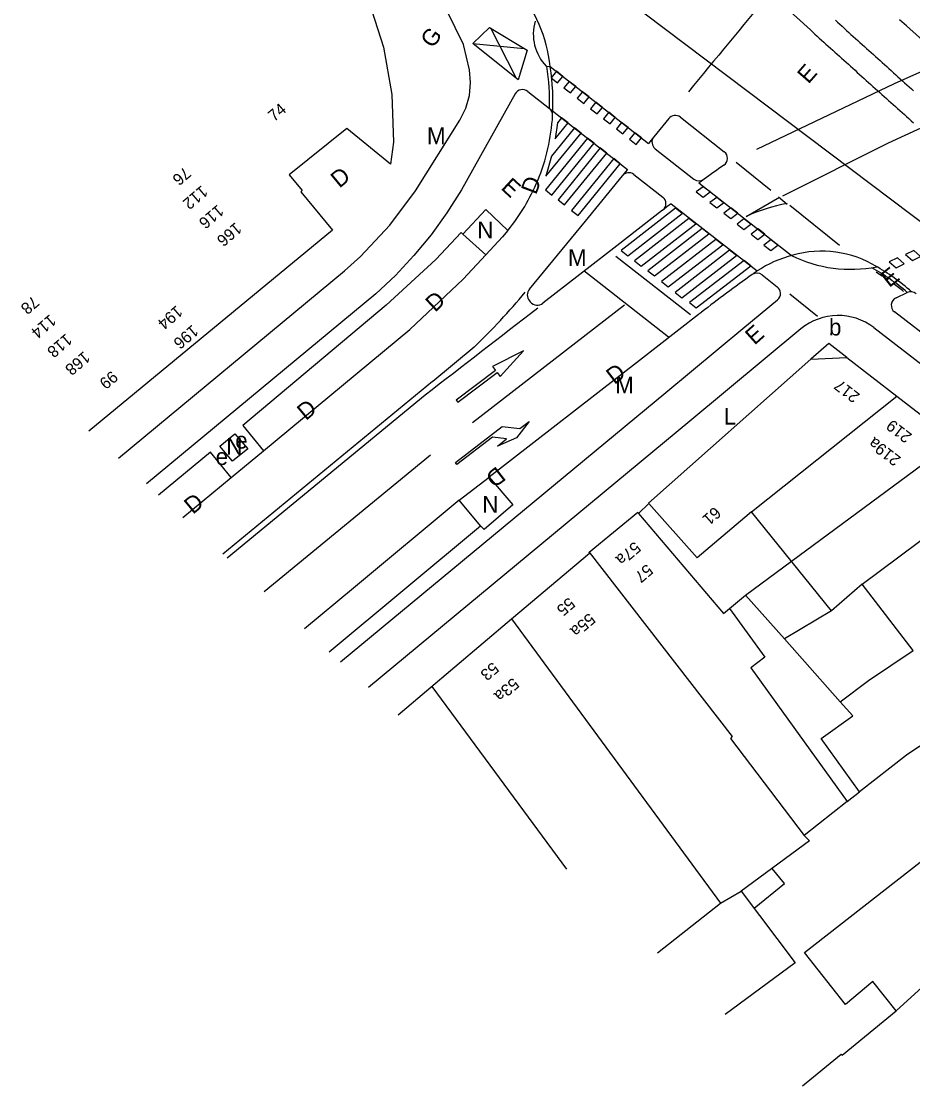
# Model space of a CAD drawing. Extents: x 81617 to 82144, y 454649 to 455150.
# Drawn here: x 81644.1 to 81697.5, y 454675.9 to 454739.6 of the extents above; entities that cross this region are included whole.
import ezdxf

# ---------------------------------------------------------------- set-up
doc = ezdxf.new("R2010")
doc.units = 0
doc.layers.add('B-WE-OG-TOPOGRAFIE-G', color=7, linetype='Continuous')
doc.layers.add('B-WE-VW-MARKERING-G', color=7, linetype='Continuous')

msp = doc.modelspace()

# ---------------------------------------------------------------- linework, layer by layer
at = {"layer": 'B-WE-OG-TOPOGRAFIE-G'}
for p, q in [((81675.519, 454736.911), (81675.741, 454736.896)), ((81675.741, 454736.896), (81681.634, 454732.285)), ((81674.403, 454735.404), (81675.706, 454734.384)), ((81675.706, 454734.384), (81680.373, 454730.732)), ((81682.848, 454733.778), (81681.955, 454732.68)), ((81683.544, 454733.856), (81686.175, 454731.792)), ((81681.955, 454732.68), (81681.634, 454732.285)), ((81682.035, 454731.971), (81684.36, 454730.151)), ((81680.063, 454730.351), (81677.85, 454727.627)), ((81680.373, 454730.732), (81680.063, 454730.351)), ((81680.76, 454730.43), (81682.487, 454729.078)), ((81684.657, 454729.919), (81690.172, 454725.604)), ((81682.995, 454728.68), (81688.146, 454724.65)), ((81677.85, 454727.627), (81674.501, 454723.568)), ((81671.903, 454725.607), (81670.521, 454726.86)), ((81688.439, 454724.42), (81689.35, 454723.708)), ((81665.305, 454723.274), (81651.571, 454711.895)), ((81696.457, 454723.047), (81697.123, 454723.364)), ((81674.509, 454722.859), (81674.561, 454722.798)), ((81684.628, 454722.04), (81681.091, 454719.294)), ((81699.533, 454719.756), (81696.366, 454722.2)), ((81692.444, 454720.301), (81691.36, 454719.373)), ((81693.506, 454719.47), (81692.444, 454720.301)), ((81687.809, 454710.22), (81696.504, 454717.158)), ((81690.199, 454707.264), (81699.968, 454714.488)), ((81656.655, 454712.276), (81658.584, 454713.883)), ((81653.762, 454709.885), (81656.655, 454712.276)), ((81670.307, 454710.92), (81672.094, 454712.308)), ((81671.585, 454709.381), (81670.307, 454710.92)), ((81681.045, 454710.132), (81681.659, 454710.717)), ((81694.423, 454705.904), (81700, 454710.044)), ((81662.521, 454701.853), (81671.585, 454709.381)), ((81686.485, 454704.429), (81687.454, 454705.234)), ((81673.439, 454703.812), (81685.954, 454686.794)), ((81689.771, 454702.623), (81693.12, 454698.851)), ((81693.53, 454692.873), (81694.275, 454693.457)), ((81689.77, 454687.969), (81689.035, 454688.872)), ((81685.954, 454686.794), (81687.192, 454687.509)), ((81687.958, 454686.496), (81689.77, 454687.969)), ((81696.461, 454680.345), (81700, 454683.576))]:
    msp.add_line(p, q, dxfattribs=at)
for points in [[(81666.167, 454761.826), (81691.328, 454739.082), (81691.328, 454739.082), (81691.461, 454738.961), (81691.595, 454738.84), (81691.729, 454738.719), (81691.863, 454738.598), (81691.996, 454738.478), (81692.13, 454738.357), (81692.264, 454738.236), (81692.398, 454738.115), (81692.532, 454737.994), (81692.665, 454737.873), (81692.799, 454737.752), (81692.933, 454737.631), (81693.067, 454737.51), (81693.201, 454737.39), (81693.335, 454737.269), (81693.468, 454737.148), (81693.602, 454737.027), (81693.736, 454736.906), (81693.87, 454736.785), (81694.004, 454736.665), (81694.138, 454736.544), (81694.272, 454736.423), (81694.406, 454736.302), (81694.54, 454736.182), (81694.674, 454736.061), (81694.808, 454735.94), (81694.942, 454735.819), (81695.076, 454735.699), (81695.21, 454735.578), (81695.344, 454735.457), (81695.479, 454735.337), (81695.613, 454735.216), (81695.747, 454735.096), (81695.881, 454734.975), (81696.016, 454734.855), (81696.15, 454734.734), (81696.284, 454734.614), (81696.418, 454734.493), (81696.553, 454734.373), (81696.553, 454734.373), (81696.687, 454734.252), (81696.822, 454734.132), (81696.956, 454734.011), (81697.091, 454733.891), (81697.226, 454733.771), (81697.36, 454733.65), (81697.495, 454733.53)], [(81670.568, 454738.214), (81669.091, 454741.249), (81668.201, 454742.903), (81667.143, 454744.591), (81666.308, 454745.728), (81665.415, 454746.82), (81664.464, 454747.862)], [(81664.894, 454740.79), (81665.775, 454738.056), (81666.269, 454735.227), (81666.365, 454732.357), (81666.198, 454731.046), (81663.567, 454733.177), (81660.121, 454730.415), (81660.901, 454729.465), (81660.815, 454729.388), (81662.719, 454727.096)], [(81692.825, 454739.663), (81692.959, 454739.542), (81693.092, 454739.421), (81693.226, 454739.3), (81693.36, 454739.18), (81693.494, 454739.059), (81693.627, 454738.938), (81693.761, 454738.817), (81693.895, 454738.696), (81694.029, 454738.576), (81694.162, 454738.455), (81694.296, 454738.334), (81694.43, 454738.213), (81694.564, 454738.092), (81694.697, 454737.972), (81694.831, 454737.851), (81694.965, 454737.73), (81695.099, 454737.61), (81695.233, 454737.489), (81695.367, 454737.368), (81695.5, 454737.248), (81695.634, 454737.127), (81695.768, 454737.007), (81695.902, 454736.886), (81696.036, 454736.765), (81696.17, 454736.645), (81696.304, 454736.524), (81696.438, 454736.404), (81696.572, 454736.284), (81696.706, 454736.163), (81696.84, 454736.043), (81696.974, 454735.922), (81697.108, 454735.802), (81697.242, 454735.682), (81697.376, 454735.562), (81697.51, 454735.441)], [(81731.982, 454708.032), (81697.077, 454739.337), (81697.077, 454739.337), (81696.942, 454739.457), (81696.808, 454739.577), (81696.674, 454739.698)], [(81667.684, 454729.457), (81670.339, 454733.689), (81670.694, 454734.393), (81670.923, 454735.155), (81670.986, 454735.928), (81670.928, 454736.691), (81670.568, 454738.214)], [(81673.659, 454735.254), (81670.435, 454729.503), (81669.57, 454728.132)], [(81649.895, 454713.432), (81663.43, 454724.654), (81664.386, 454725.517), (81666.145, 454727.394), (81667.684, 454729.457)], [(81670.521, 454726.86), (81671.896, 454728.323), (81673.215, 454727.075)], [(81682.484, 454728.289), (81679.734, 454726.153)], [(81669.57, 454728.132), (81668.621, 454726.819), (81667.591, 454725.568), (81666.484, 454724.385), (81665.305, 454723.274)], [(81662.719, 454727.096), (81648.125, 454715.055)], [(81670.521, 454726.86), (81670.425, 454726.948), (81668.903, 454725.346), (81665.935, 454722.606), (81657.348, 454715.394), (81658.584, 454713.883)], [(81673.215, 454727.075), (81672.899, 454726.686), (81671.903, 454725.607)], [(81673.215, 454727.075), (81672.899, 454726.686), (81671.903, 454725.607)], [(81679.734, 454726.153), (81675.316, 454722.723)], [(81658.584, 454713.883), (81667.339, 454721.154), (81670.536, 454724.153), (81671.903, 454725.607)], [(81682.675, 454717.381), (81687.29, 454721.203), (81689.362, 454722.93)], [(81690.761, 454721.18), (81684.105, 454715.66)], [(81695.133, 454721.257), (81710.923, 454709.073), (81719.683, 454702.175)], [(81681.091, 454719.294), (81672.094, 454712.308)], [(81681.659, 454710.717), (81681.638, 454710.746), (81691.36, 454719.373), (81693.506, 454719.47), (81696.504, 454717.158), (81700, 454714.463)], [(81663.187, 454701.242), (81682.675, 454717.381)], [(81684.105, 454715.66), (81664.864, 454699.703)], [(81657.638, 454713.992), (81656.728, 454713.26), (81655.96, 454714.155), (81656.866, 454714.904), (81657.638, 454713.992)], [(81656.655, 454712.276), (81655.406, 454713.794), (81652.298, 454711.228)], [(81672.094, 454712.308), (81673.52, 454710.648), (81671.789, 454709.162), (81671.585, 454709.381)], [(81670.307, 454710.92), (81663.97, 454705.661), (81661.031, 454703.219)], [(81700, 454693.76), (81699.888, 454693.884), (81697.881, 454696.204), (81697.087, 454695.661), (81694.275, 454693.457), (81691.968, 454696.655), (81693.864, 454698.013), (81693.12, 454698.851), (81694.811, 454700.118), (81697.487, 454701.918), (81694.423, 454705.904), (81692.598, 454704.296), (81687.809, 454710.22), (81687.395, 454709.889), (81684.558, 454707.482), (81681.659, 454710.717)], [(81666.647, 454698.069), (81673.439, 454703.812), (81678.1, 454707.752), (81678.082, 454707.815), (81680.988, 454710.202), (81681.045, 454710.132)], [(81681.045, 454710.132), (81686.127, 454704.132), (81686.485, 454704.429), (81688.598, 454701.527), (81687.773, 454700.88), (81693.53, 454692.873), (81690.948, 454690.849), (81691.274, 454690.528), (81687.192, 454687.509), (81690.426, 454683.228), (81686.219, 454680.119)], [(81678.082, 454707.815), (81686.64, 454696.766), (81686.54, 454696.658), (81690.948, 454690.849)], [(81692.598, 454704.296), (81689.771, 454702.623), (81687.454, 454705.234), (81690.199, 454707.264)], [(81668.655, 454699.767), (81676.731, 454688.82)], [(81690.86, 454675.862), (81693.167, 454677.748), (81693.226, 454677.694), (81696.461, 454680.345), (81695.069, 454682.109), (81693.441, 454680.727), (81690.98, 454683.836), (81700, 454690.889)], [(81682.179, 454683.824), (81685.954, 454686.794)]]:
    msp.add_lwpolyline(points, dxfattribs=at)
for centre, radius, start, end in [((81667.367, 454736.072), 8.414, 5.61736, 41.24927), ((81677.483, 454738.825), 2.743, 163.56997, 224.26272), ((81674.095, 454735.01), 0.5, 51.95732, 150.7285), ((81663.917, 454734.661), 12, 337.46595, 356.65409), ((81675.398, 454733.99), 0.5, 356.65409, 51.95732), ((81683.236, 454733.463), 0.5, 51.87473, 140.91169), ((81682.343, 454732.365), 0.5, 140.91169, 231.95732), ((81685.866, 454731.399), 0.5, 305.04981, 51.87473), ((81743.582, 454649.124), 100, 125.04981, 125.88829), ((81680.452, 454730.036), 0.5, 51.95732, 140.91169), ((81684.669, 454730.545), 0.5, 231.95732, 305.88829), ((81743.582, 454649.124), 100, 125.88829, 126.10378), ((81663.917, 454734.661), 12, 320.91169, 337.46595), ((81682.179, 454728.684), 0.5, 307.66054, 51.95732), ((81743.582, 454649.124), 100, 127.2916, 127.66054), ((81692.001, 454719.529), 6.308, 58.38506, 105.91347), ((81692.031, 454718.774), 7.044, 104.46027, 123.46789), ((81693.748, 454732.794), 8.046, 243.79663, 281.17558), ((81745.959, 454643.057), 100, 125.53419, 127.69775), ((81688.131, 454724.027), 0.5, 51.95732, 125.53419), ((81692.104, 454718.876), 7, 124.43137, 127.06323), ((81674.926, 454723.218), 0.55, 140.4727, 220.72473), ((81689.042, 454723.314), 0.5, 309.80557, 51.95732), ((81697.338, 454722.913), 0.5, 48.09943, 115.44696), ((81674.978, 454723.157), 0.55, 220.72473, 307.82968), ((81696.672, 454722.596), 0.5, 115.44696, 232.34591), ((81745.959, 454643.057), 100, 127.69775, 127.82968), ((81692.995, 454718.486), 3.5, 52.34591, 129.66966)]:
    msp.add_arc(centre, radius, start, end, dxfattribs=at)
at = {"layer": 'B-WE-VW-MARKERING-G'}
for p, q in [((81678.314, 454742.411), (81698.634, 454727.077)), ((81672.168, 454739.2), (81673.672, 454736.267)), ((81671.123, 454738.267), (81674.199, 454737.97)), ((81687.488, 454727.919), (81689.477, 454729.074)), ((81689.423, 454729.088), (81689.934, 454728.65)), ((81677.755, 454724.677), (81682.831, 454720.705)), ((81671.099, 454715.57), (81680.196, 454722.623)), ((81671.201, 454720.085), (81668.716, 454718.027)), ((81668.713, 454718.03), (81656.154, 454707.692)), ((81668.272, 454717.21), (81656.409, 454707.458)), ((81674.489, 454715.636), (81673.723, 454714.665)), ((81673.935, 454715.208), (81674.489, 454715.636)), ((81670.075, 454713.171), (81672.883, 454715.343)), ((81672.883, 454715.343), (81673.935, 454715.208)), ((81672.303, 454714.704), (81670.167, 454713.053)), ((81673.144, 454714.597), (81672.303, 454714.704)), ((81673.723, 454714.665), (81672.591, 454714.168)), ((81672.591, 454714.168), (81673.144, 454714.597)), ((81668.579, 454713.628), (81658.622, 454705.429)), ((81670.167, 454713.053), (81670.075, 454713.171))]:
    msp.add_line(p, q, dxfattribs=at)
for points in [[(81689.688, 454729.154), (81696.008, 454732.316), (81704.216, 454736.092), (81716.472, 454741.453)], [(81688.131, 454731.94), (81696.375, 454735.872), (81698.635, 454736.901)], [(81686.876, 454731.173), (81688.964, 454729.498)], [(81690.094, 454728.592), (81693.07, 454726.204)], [(81679.685, 454725.535), (81684.153, 454722.039)], [(81690.09, 454723.277), (81691.765, 454721.934)]]:
    msp.add_lwpolyline(points, dxfattribs=at)
for points in [[(81671.123, 454738.267), (81672.109, 454739.227), (81674.37, 454737.862), (81673.834, 454736.095)], [(81676.512, 454736.299), (81676.118, 454736.607), (81675.802, 454736.219), (81676.196, 454735.911)], [(81677.284, 454735.695), (81676.89, 454736.003), (81676.575, 454735.615), (81676.968, 454735.307)], [(81678.082, 454735.07), (81677.689, 454735.378), (81677.373, 454734.99), (81677.767, 454734.682)], [(81678.881, 454734.445), (81678.487, 454734.753), (81678.172, 454734.365), (81678.566, 454734.057)], [(81679.649, 454733.845), (81679.255, 454734.153), (81678.94, 454733.765), (81679.334, 454733.456)], [(81676.826, 454733.514), (81676.432, 454733.822), (81676.191, 454733.526), (81676.055, 454732.565)], [(81680.421, 454733.241), (81680.027, 454733.549), (81679.712, 454733.161), (81680.106, 454732.853)], [(81677.598, 454732.91), (81677.204, 454733.218), (81675.828, 454731.524), (81675.498, 454730.325)], [(81681.215, 454732.619), (81680.821, 454732.927), (81680.506, 454732.539), (81680.9, 454732.231)], [(81678.379, 454732.299), (81677.985, 454732.607), (81675.462, 454729.502), (81675.856, 454729.194)], [(81679.138, 454731.706), (81678.744, 454732.014), (81676.222, 454728.909), (81676.615, 454728.601)], [(81679.95, 454731.07), (81679.556, 454731.378), (81677.033, 454728.273), (81677.427, 454727.965)], [(81685.322, 454729.379), (81684.913, 454729.698), (81684.498, 454729.389), (81684.906, 454729.069)], [(81686.135, 454728.736), (81685.727, 454729.056), (81685.311, 454728.746), (81685.719, 454728.427)], [(81683.662, 454728.086), (81683.254, 454728.406), (81679.992, 454725.879), (81680.398, 454725.561)], [(81686.978, 454728.103), (81686.57, 454728.422), (81686.154, 454728.113), (81686.562, 454727.793)], [(81684.465, 454727.469), (81684.057, 454727.789), (81680.796, 454725.262), (81681.202, 454724.944)], [(81687.759, 454727.452), (81687.351, 454727.771), (81686.936, 454727.462), (81687.344, 454727.142)], [(81685.257, 454726.876), (81684.849, 454727.195), (81681.588, 454724.668), (81681.994, 454724.351)], [(81688.603, 454726.849), (81688.195, 454727.168), (81687.779, 454726.858), (81688.187, 454726.539)], [(81686.08, 454726.218), (81685.672, 454726.537), (81682.411, 454724.01), (81682.817, 454723.693)], [(81689.375, 454726.194), (81688.967, 454726.513), (81688.551, 454726.204), (81688.959, 454725.884)], [(81686.897, 454725.573), (81686.489, 454725.892), (81683.227, 454723.365), (81683.634, 454723.048)], [(81697.927, 454725.519), (81697.52, 454725.879), (81697.029, 454725.645), (81697.436, 454725.285)], [(81687.764, 454724.965), (81687.355, 454725.284), (81684.094, 454722.757), (81684.5, 454722.439)], [(81696.948, 454725.075), (81696.541, 454725.435), (81696.051, 454725.202), (81696.458, 454724.841)], [(81674.156, 454719.868), (81672.295, 454718.93), (81672.476, 454718.691), (81670.123, 454716.911), (81670.214, 454716.791), (81672.566, 454718.571), (81672.747, 454718.332)]]:
    msp.add_lwpolyline(points, close=True, dxfattribs=at)
for centre, radius, start, end in [((83492.28, 453246.905), 2342.079, 140.169378, 140.540083), ((81661.389, 454734.734), 14.328, 358.57939, 8.73167), ((81661.389, 454734.734), 14.528, 356.95176, 8.50812), ((81692.014, 454717.772), 11.111, 100.81313, 114.04018), ((81688.818, 454713.695), 12.751, 49.32793, 60.98455), ((81688.818, 454713.695), 12.951, 48.60466, 60.40218), ((81688.437, 454713.023), 13.414, 55.75821, 59.41292), ((81688.437, 454713.023), 13.414, 50.80229, 54.18653), ((81639.242, 454752.805), 45.741, 314.32623, 319.95347), ((82380.944, 453802.794), 1159.334, 127.511498, 127.931913)]:
    msp.add_arc(centre, radius, start, end, dxfattribs=at)

# ---------------------------------------------------------------- texts
at = {"layer": 'B-WE-OG-TOPOGRAFIE-G'}
for s, height, rotation, p in [('G', 1, 54.20164, (81668.72, 454737.937)), ('E', 1, 48.83265, (81691.21, 454735.81)), ('74', 0.7, 40.11061, (81659.22, 454733.555)), ('76', 0.7, 220.3698, (81653.864, 454730.919)), ('D', 1, 39.55066, (81663.129, 454729.573)), ('E', 1, 317.23229, (81672.752, 454729.583)), ('D', 1, 69.18376, (81674.903, 454729.173)), ('112', 0.7, 220.3698, (81654.883, 454729.816)), ('116', 0.7, 220.3698, (81655.841, 454728.661)), ('166', 0.7, 220.3698, (81656.915, 454727.606)), ('E', 1, 38.51962, (81696.05, 454723.623)), ('78', 0.7, 220.3698, (81644.78, 454723.196)), ('D', 1, 43.36353, (81668.859, 454722.144)), ('194', 0.7, 220.3698, (81653.375, 454722.628)), ('114', 0.7, 220.3698, (81645.799, 454722.093)), ('196', 0.7, 220.3698, (81654.321, 454721.463)), ('E', 1, 41.78888, (81687.984, 454720.175)), ('118', 0.7, 220.3698, (81646.758, 454720.94)), ('168', 0.7, 220.3698, (81647.832, 454719.884)), ('66', 0.7, 39.52485, (81649.14, 454717.513)), ('D', 1, 37.75807, (81679.596, 454717.812)), ('217', 0.7, 142.37261, (81694.342, 454717.247)), ('D', 1, 39.8055, (81661.121, 454715.657)), ('219', 0.7, 142.37261, (81697.463, 454714.842)), ('219a', 0.7, 142.37261, (81696.796, 454713.463)), ('D', 1, 217.77083, (81672.559, 454712.99)), ('D', 1, 39.73236, (81654.356, 454710.043)), ('61', 0.7, 221.58815, (81685.589, 454710.576)), ('57a', 0.7, 220.34937, (81680.802, 454708.485)), ('57', 0.7, 220.34937, (81681.532, 454707.138)), ('55', 0.7, 220.34937, (81676.867, 454705.143)), ('55a', 0.7, 220.34937, (81678.08, 454704.205)), ('53', 0.7, 220.34937, (81672.305, 454701.267)), ('53a', 0.7, 220.34937, (81673.517, 454700.329))]:
    msp.add_text(s, height=height, rotation=rotation, dxfattribs=at).set_placement(p)
for s, p in [('M', (81668.371, 454732.242)), ('N', (81671.38, 454726.605)), ('M', (81676.815, 454724.953)), ('b', (81692.444, 454720.786)), ('M', (81679.641, 454717.323)), ('L', (81686.143, 454715.45)), ('N', (81656.358, 454713.651)), ('e', (81656.892, 454714.013)), ('e', (81655.719, 454713.031)), ('N', (81671.686, 454710.168))]:
    msp.add_text(s, height=1, dxfattribs=at).set_placement(p)

doc.saveas('drawing.dxf')
